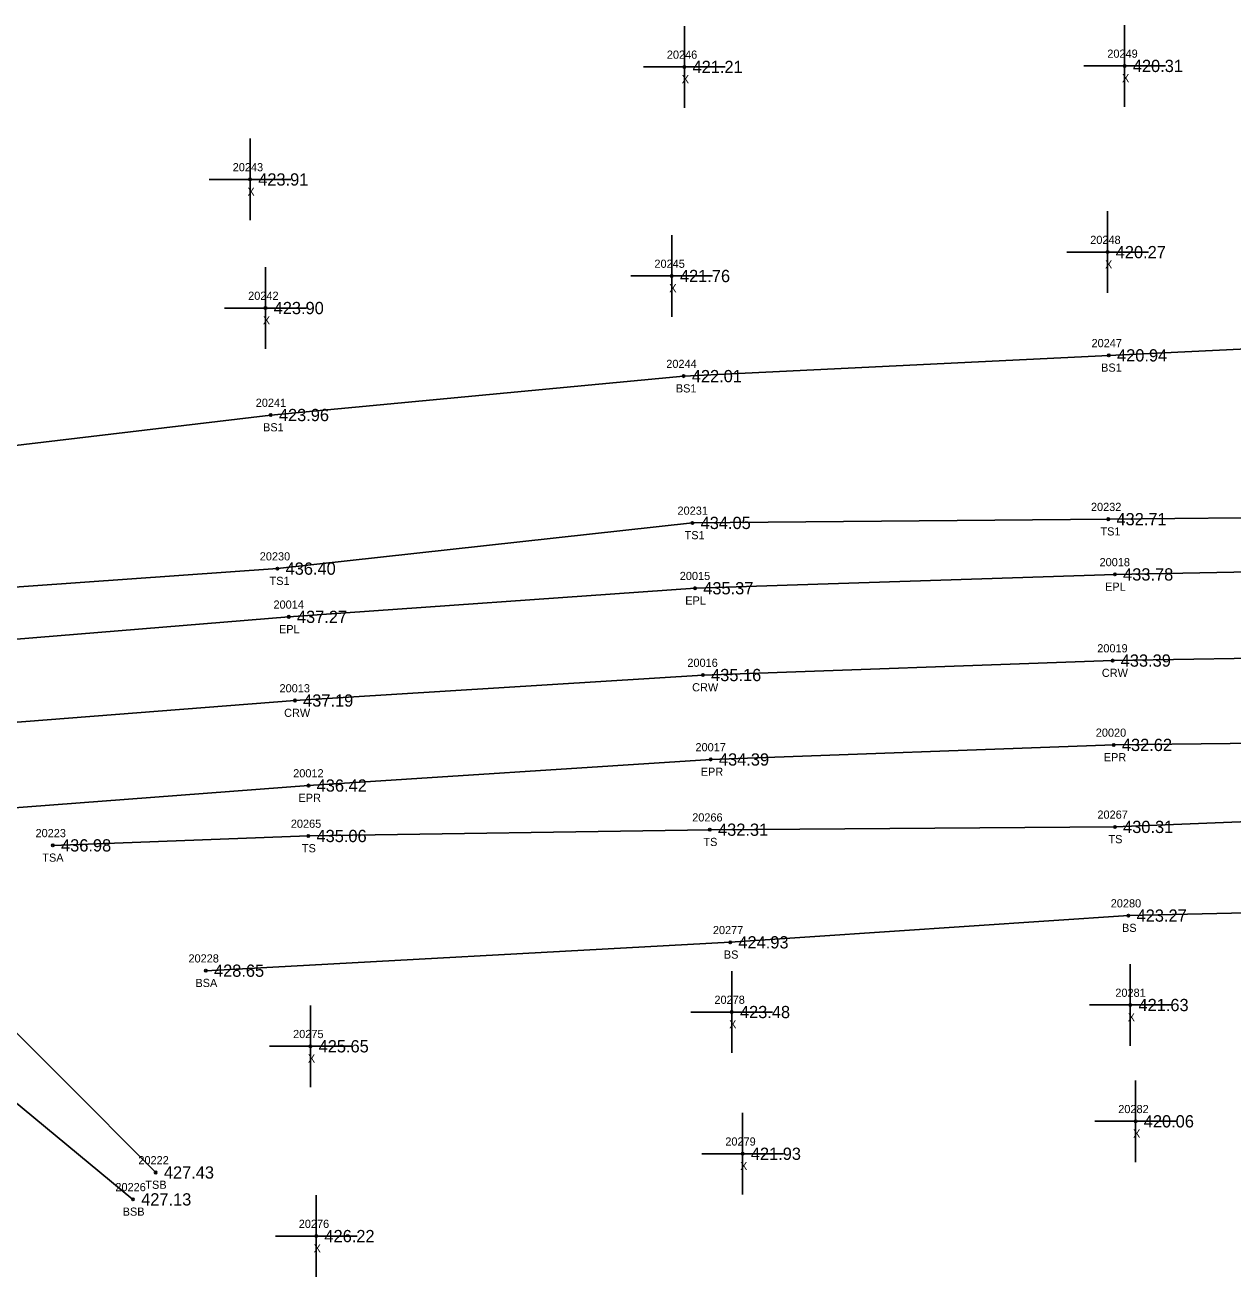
# Model space of a CAD drawing. Extents: x 1613184 to 1614731, y 770859 to 771868.
# Drawn here: x 1613509.6 to 1613657.4, y 771280.4 to 771433.6 of the extents above; entities that cross this region are included whole.
import ezdxf

# ---------------------------------------------------------------- set-up
doc = ezdxf.new("R2010")
doc.units = 0
for name, color, linetype in [('RD_DTM_BkLn1', 7, 'Continuous'), ('RD_DTM_BkLn2', 7, 'Continuous'), ('RD_DTM_BkLn_txCode', 7, 'Continuous'), ('RD_EX_Misc', 7, 'Continuous'), ('RD_EX_Misc_txCode', 7, 'Continuous'), ('RD_EX_Road', 7, 'Continuous'), ('RD_EX_Road_txCode', 7, 'Continuous'), ('RD_EX_TX_Misc_ELEV', 7, 'Continuous'), ('RD_EX_TX_Road_ELEV', 7, 'Continuous'), ('RD_HC_Survey_ELEV', 7, 'Continuous'), ('RD_HC_Survey_txCode', 7, 'Continuous'), ('RD_SMD_Locator', 7, 'Continuous')]:
    doc.layers.add(name, color=color, linetype=linetype)

msp = doc.modelspace()

# ---------------------------------------------------------------- linework, layer by layer
at = {"layer": 'RD_DTM_BkLn1'}
msp.add_lwpolyline([(1613193.64, 771319.41), (1613293.11, 771329.14), (1613392.46, 771338.5), (1613492.95, 771347.08), (1613542.61, 771350.97), (1613592.52, 771354.09), (1613642.63, 771355.86), (1613692.27, 771356.69), (1613742.08, 771356.79), (1613792.13, 771355.6), (1613841.94, 771351.86), (1613890.87, 771346.48)], dxfattribs=at)
at = {"layer": 'RD_DTM_BkLn2'}
for points in [[(1613191.9, 771337.48), (1613291.44, 771345.53), (1613389.08, 771355.5), (1613435.73, 771361.94), (1613448.05, 771379.9), (1613456.58, 771373.81), (1613489.82, 771379.95), (1613539.65, 771385.9), (1613590.16, 771390.66), (1613642.18, 771393.2), (1613691.23, 771395.53), (1613743.12, 771392.35), (1613794.87, 771390.82), (1613846.37, 771384.69), (1613895.3, 771384.28), (1613914.84, 771377.38)], [(1613192.28, 771333.37), (1613291.74, 771342.64), (1613389.11, 771353.66), (1613436.85, 771356.33), (1613492.16, 771363.71), (1613540.47, 771367.11), (1613591.24, 771372.7), (1613642.11, 771373.16), (1613691.12, 771373.65), (1613744.36, 771374.73), (1613793.64, 771374.02), (1613845.39, 771367.84), (1613892.43, 771366.82), (1613891.67, 771360.8)], [(1613513, 771333.25), (1613544.25, 771334.4), (1613593.37, 771335.17), (1613642.92, 771335.51), (1613693.05, 771337.53), (1613742.72, 771338.4), (1613791.72, 771337.06), (1613840.42, 771334.43), (1613870.28, 771332.34), (1613884.67, 771331.69), (1613888.61, 771333.71)], [(1613195.19, 771306.21), (1613295.11, 771315.27), (1613393.64, 771323.81), (1613454.01, 771327.14), (1613491.18, 771327.74), (1613525.58, 771293.23)], [(1613531.71, 771317.92), (1613595.86, 771321.39), (1613644.57, 771324.66), (1613693.19, 771325.79), (1613742.08, 771324.98), (1613790.16, 771325.78), (1613839.02, 771321.26), (1613886.56, 771314.77), (1613914.71, 771327.05)], [(1613195.67, 771302.8), (1613295.8, 771311.41), (1613393.76, 771321.05), (1613452.01, 771322.58), (1613487.68, 771317.36), (1613495.9, 771312.14), (1613522.8, 771289.94)]]:
    msp.add_lwpolyline(points, dxfattribs=at)
at = {"layer": 'RD_EX_Misc'}
for p, q in [((1613590.25, 771423.49), (1613590.25, 771433.49)), ((1613644.11, 771423.61), (1613644.11, 771433.61)), ((1613585.25, 771428.49), (1613595.25, 771428.49)), ((1613639.11, 771428.61), (1613649.11, 771428.61)), ((1613537.12, 771409.72), (1613537.12, 771419.72)), ((1613532.12, 771414.72), (1613542.12, 771414.72)), ((1613642.02, 771400.83), (1613642.02, 771410.83)), ((1613588.71, 771397.91), (1613588.71, 771407.91)), ((1613637.02, 771405.83), (1613647.02, 771405.83)), ((1613539.01, 771393.99), (1613539.01, 771403.99)), ((1613583.71, 771402.91), (1613593.71, 771402.91)), ((1613534.01, 771398.99), (1613544.01, 771398.99)), ((1613644.8, 771308.72), (1613644.8, 771318.72)), ((1613596.05, 771307.86), (1613596.05, 771317.86)), ((1613544.51, 771303.67), (1613544.51, 771313.67)), ((1613639.8, 771313.72), (1613649.8, 771313.72)), ((1613591.05, 771312.86), (1613601.05, 771312.86)), ((1613539.51, 771308.67), (1613549.51, 771308.67)), ((1613645.45, 771294.49), (1613645.45, 771304.49)), ((1613597.38, 771290.52), (1613597.38, 771300.52)), ((1613640.45, 771299.49), (1613650.45, 771299.49)), ((1613592.38, 771295.52), (1613602.38, 771295.52)), ((1613545.22, 771280.45), (1613545.22, 771290.45)), ((1613540.22, 771285.45), (1613550.22, 771285.45))]:
    msp.add_line(p, q, dxfattribs=at)
at = {"layer": 'RD_EX_Road'}
for points in [[(1613192.48, 771329.15), (1613292.05, 771338.23), (1613391, 771348.45), (1613492.61, 771357.17), (1613541.86, 771361.21), (1613591.56, 771364.71), (1613642.92, 771366.4), (1613692.81, 771367.35), (1613742.66, 771367.02), (1613792.19, 771365.04), (1613843.32, 771361.63), (1613887.78, 771357.57), (1613892.3, 771358.63)], [(1613194.6, 771309.27), (1613294.55, 771318.15), (1613393.75, 771328.31), (1613493.74, 771336.74), (1613544.27, 771340.57), (1613593.48, 771343.76), (1613642.77, 771345.54), (1613692.58, 771346.11), (1613741.71, 771345.82), (1613791.79, 771344.79), (1613840.79, 771341.46), (1613889.25, 771335.84)]]:
    msp.add_lwpolyline(points, dxfattribs=at)
at = {"layer": 'RD_SMD_Locator'}
for centre in [(1613590.25, 771428.49), (1613644.11, 771428.61), (1613537.12, 771414.72), (1613642.02, 771405.83), (1613588.71, 771402.91), (1613539.01, 771398.99), (1613642.18, 771393.2), (1613590.16, 771390.66), (1613539.65, 771385.9), (1613642.11, 771373.16), (1613591.24, 771372.7), (1613540.47, 771367.11), (1613642.92, 771366.4), (1613591.56, 771364.71), (1613541.86, 771361.21), (1613642.63, 771355.86), (1613592.52, 771354.09), (1613542.61, 771350.97), (1613642.77, 771345.54), (1613593.48, 771343.76), (1613544.27, 771340.57), (1613593.37, 771335.17), (1613642.92, 771335.51), (1613513, 771333.25), (1613544.25, 771334.4), (1613644.57, 771324.66), (1613595.86, 771321.39), (1613531.71, 771317.92), (1613644.8, 771313.72), (1613596.05, 771312.86), (1613544.51, 771308.67), (1613645.45, 771299.49), (1613597.38, 771295.52), (1613525.58, 771293.23), (1613522.8, 771289.94), (1613545.22, 771285.45)]:
    msp.add_circle(centre, 0.15, dxfattribs=at)

# ---------------------------------------------------------------- texts
at = {"layer": 'RD_DTM_BkLn_txCode'}
for s, p in [('20247', (1613640.06, 771394.2)), ('20244', (1613588.04, 771391.66)), ('BS1', (1613641.23, 771391.2)), ('BS1', (1613589.21, 771388.66)), ('20241', (1613537.82, 771386.9)), ('BS1', (1613538.71, 771383.9)), ('20232', (1613639.99, 771374.16)), ('20231', (1613589.41, 771373.7)), ('TS1', (1613590.28, 771370.7)), ('TS1', (1613641.15, 771371.16)), ('20230', (1613538.31, 771368.11)), ('TS1', (1613539.51, 771365.11)), ('20266', (1613591.21, 771336.17)), ('20267', (1613640.78, 771336.51)), ('20223', (1613510.88, 771334.25)), ('20265', (1613542.11, 771335.4)), ('TS', (1613543.46, 771332.4)), ('TS', (1613592.58, 771333.17)), ('TS', (1613642.13, 771333.51)), ('TSA', (1613511.71, 771331.25)), ('20280', (1613642.41, 771325.66)), ('20277', (1613593.74, 771322.39)), ('BS', (1613643.79, 771322.66)), ('20228', (1613529.59, 771318.92)), ('BS', (1613595.08, 771319.39)), ('BSA', (1613530.44, 771315.92)), ('20222', (1613523.46, 771294.23)), ('TSB', (1613524.31, 771291.23)), ('20226', (1613520.65, 771290.94)), ('BSB', (1613521.54, 771287.94))]:
    msp.add_text(s, height=1, dxfattribs=at).set_placement(p)
at = {"layer": 'RD_EX_Misc_txCode'}
for s, p in [('20246', (1613588.11, 771429.49)), ('20249', (1613641.99, 771429.61)), ('X', (1613589.93, 771426.49)), ('X', (1613643.79, 771426.61)), ('20243', (1613535, 771415.72)), ('X', (1613536.8, 771412.72)), ('20248', (1613639.9, 771406.83)), ('20245', (1613586.59, 771403.91)), ('X', (1613641.71, 771403.83)), ('20242', (1613536.89, 771399.99)), ('X', (1613588.4, 771400.91)), ('X', (1613538.69, 771396.99)), ('20281', (1613642.97, 771314.72)), ('20278', (1613593.93, 771313.86)), ('X', (1613644.49, 771311.72)), ('20275', (1613542.39, 771309.67)), ('X', (1613595.73, 771310.86)), ('X', (1613544.2, 771306.67)), ('20282', (1613643.33, 771300.49)), ('X', (1613645.14, 771297.49)), ('20279', (1613595.26, 771296.52)), ('X', (1613597.07, 771293.52)), ('20276', (1613543.08, 771286.45)), ('X', (1613544.9, 771283.45))]:
    msp.add_text(s, height=1, dxfattribs=at).set_placement(p)
at = {"layer": 'RD_EX_Road_txCode'}
for s, p in [('20018', (1613641.04, 771367.4)), ('20015', (1613589.69, 771365.71)), ('EPL', (1613641.71, 771364.4)), ('20014', (1613539.99, 771362.21)), ('EPL', (1613590.36, 771362.71)), ('EPL', (1613540.66, 771359.21)), ('20020', (1613640.58, 771346.54)), ('20017', (1613591.61, 771344.76)), ('EPR', (1613641.55, 771343.54)), ('20012', (1613542.4, 771341.57)), ('EPR', (1613592.25, 771341.76)), ('EPR', (1613543.05, 771338.57))]:
    msp.add_text(s, height=1, dxfattribs=at).set_placement(p)
at = {"layer": 'RD_EX_TX_Misc_ELEV'}
for s, p in [('421.21', (1613591.25, 771427.74)), ('420.31', (1613645.11, 771427.86)), ('423.91', (1613538.12, 771413.97)), ('420.27', (1613643.02, 771405.08)), ('421.76', (1613589.71, 771402.16)), ('423.90', (1613540.01, 771398.24)), ('420.94', (1613643.18, 771392.45)), ('422.01', (1613591.16, 771389.91)), ('423.96', (1613540.65, 771385.15)), ('434.05', (1613592.24, 771371.95)), ('432.71', (1613643.11, 771372.41)), ('436.40', (1613541.47, 771366.36)), ('435.06', (1613545.25, 771333.65)), ('432.31', (1613594.37, 771334.42)), ('430.31', (1613643.92, 771334.76)), ('436.98', (1613514, 771332.5)), ('423.27', (1613645.57, 771323.91)), ('424.93', (1613596.86, 771320.64)), ('428.65', (1613532.71, 771317.17)), ('423.48', (1613597.05, 771312.11)), ('421.63', (1613645.8, 771312.97)), ('425.65', (1613545.51, 771307.92)), ('420.06', (1613646.45, 771298.74)), ('421.93', (1613598.38, 771294.77)), ('427.43', (1613526.58, 771292.48)), ('427.13', (1613523.8, 771289.19)), ('426.22', (1613546.22, 771284.7))]:
    msp.add_text(s, height=1.5, dxfattribs=at).set_placement(p)
at = {"layer": 'RD_EX_TX_Road_ELEV'}
for s, p in [('433.78', (1613643.92, 771365.65)), ('435.37', (1613592.56, 771363.96)), ('437.27', (1613542.86, 771360.46)), ('432.62', (1613643.77, 771344.79)), ('434.39', (1613594.48, 771343.01)), ('436.42', (1613545.27, 771339.82))]:
    msp.add_text(s, height=1.5, dxfattribs=at).set_placement(p)
at = {"layer": 'RD_HC_Survey_ELEV'}
for s, p in [('433.39', (1613643.63, 771355.11)), ('435.16', (1613593.52, 771353.34)), ('437.19', (1613543.61, 771350.22))]:
    msp.add_text(s, height=1.5, dxfattribs=at).set_placement(p)
at = {"layer": 'RD_HC_Survey_txCode'}
for s, p in [('20019', (1613640.76, 771356.86)), ('20016', (1613590.62, 771355.09)), ('CRW', (1613641.32, 771353.86)), ('20013', (1613540.73, 771351.97)), ('CRW', (1613591.2, 771352.09)), ('CRW', (1613541.29, 771348.97))]:
    msp.add_text(s, height=1, dxfattribs=at).set_placement(p)

doc.saveas('drawing.dxf')
